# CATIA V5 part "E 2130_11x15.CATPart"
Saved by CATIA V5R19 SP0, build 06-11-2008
Nomenclature: E 2130_11x1.5
Description: PART-E 2130_11x1.5-DESC
Property "Hersteller": "Meusburger"
Property "Material": "FPM (Viton), 80 Shore A"
Property "Bestellnummer": "E 2130/11x1.5"
Property "Teilenummer": "E 2130/11x1.5"
Property "Beschreibung": "O-Ring _ O-ring seal"
Material "Rubber": density 910 kg/m3, Young's modulus 2e+06 Pa, Poisson ratio 0.49, thermal expansion 0.000162 1/K
Bounding box of the stored display mesh (mm): x -7 to 7, y -7 to 7, z -1.2 to 0
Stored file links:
  G:\UTB\Kombinované\Bakalářská práce\Catia\FORMA\E 2130_11x15.CATPart
  D:\Aplikace\CATIA\Nová složka\win_b64\startup\materials\Catalog.CATMaterial
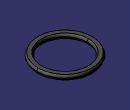
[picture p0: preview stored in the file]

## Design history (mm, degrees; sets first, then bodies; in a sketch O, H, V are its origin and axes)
Body1 "E 2130_11x1.5" (main body)
  Solid1: solid without history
